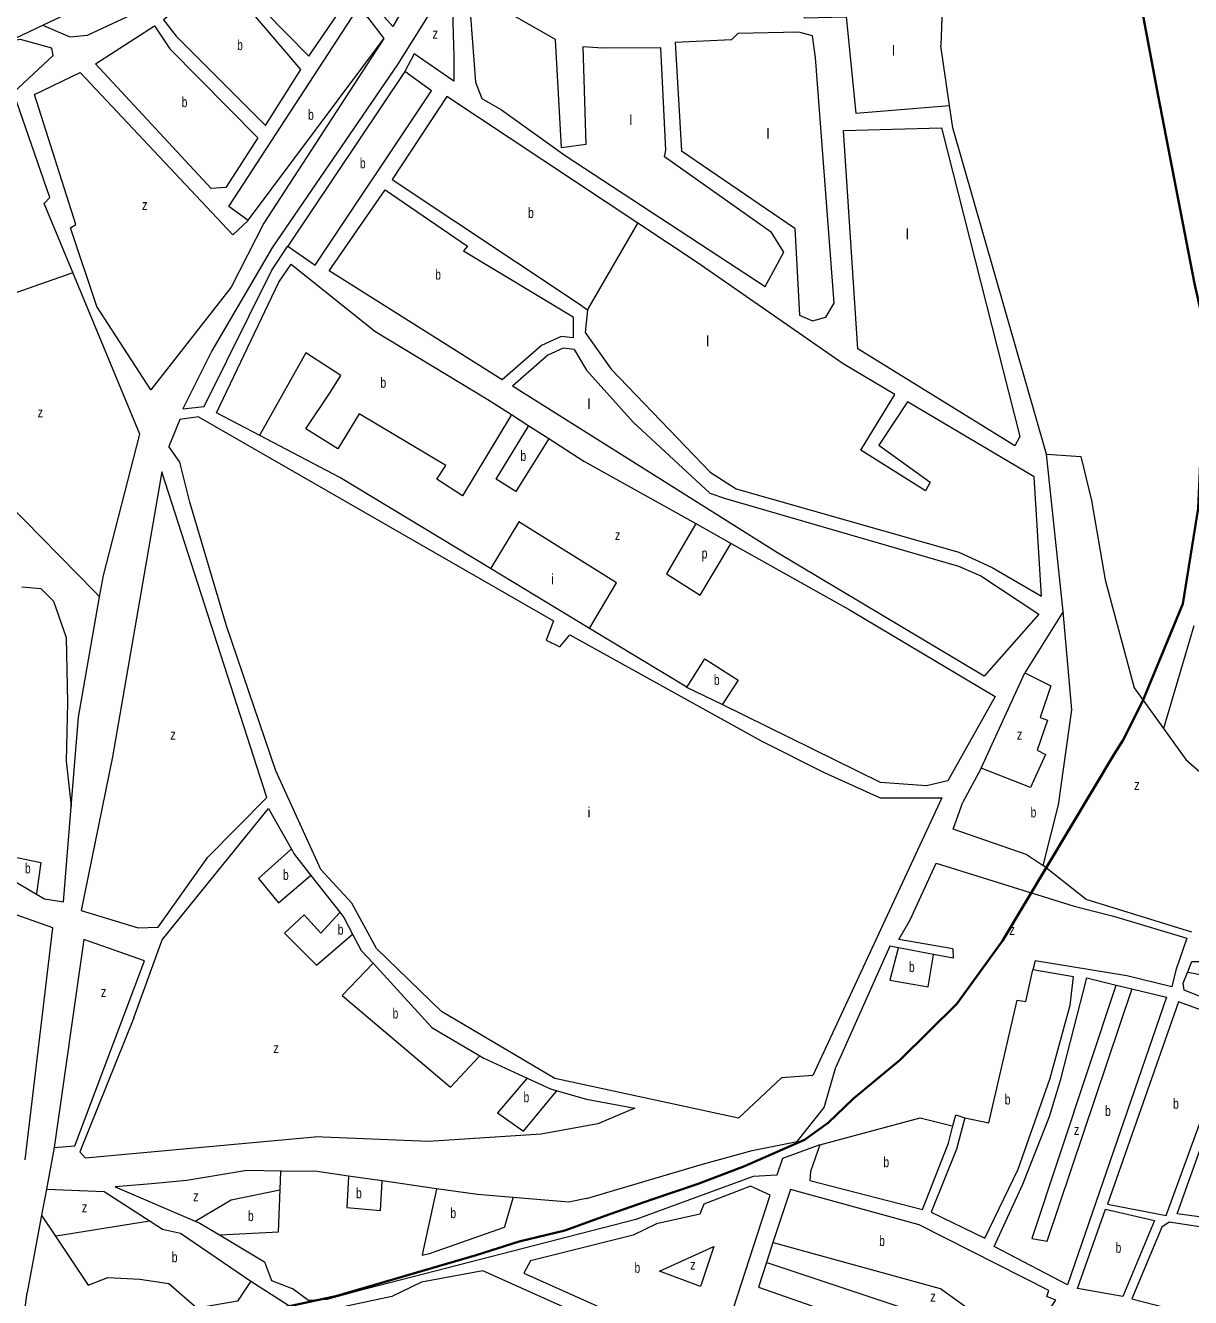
# Model space of a CAD drawing. Extents: x 639657 to 671642, y 222838 to 252123.
# Drawn here: x 646943 to 648074, y 234105 to 235340 of the extents above; entities that cross this region are included whole.
import ezdxf

# ---------------------------------------------------------------- set-up
doc = ezdxf.new("R2010")
doc.units = 0
doc.header["$LTSCALE"] = 4
for name, color, linetype, lineweight in [('1', 7, 'Continuous', 13), ('21', 7, 'Continuous', 13), ('57', 7, 'Continuous', 35)]:
    doc.layers.add(name, color=color, linetype=linetype, lineweight=lineweight)
doc.layers.add('7', color=7, linetype='Continuous')

msp = doc.modelspace()

# ---------------------------------------------------------------- linework, layer by layer
at = {"layer": '1'}
for p, q in [((647144.641, 235136.525), (647159.531, 235150.532)), ((647950.552, 234770.922), (647934.4, 234923.67)), ((647950.552, 234770.922), (647913.58, 234711.44)), ((647870.96, 234618.78), (647913.58, 234711.44)), ((647870.96, 234618.78), (647853.32, 234585.79)), ((647915.54, 234534.59), (647931.11, 234524.53)), ((647972.81, 234491.34), (647931.11, 234524.53)), ((648075.39, 234459.63), (647972.81, 234491.34)), ((646939.271, 234066.351), (646944.98, 234109.88))]:
    msp.add_line(p, q, dxfattribs=at)
for points in [[(647199.59, 235439.27), (647140.33, 235394.43), (647175.84, 235353.17), (647218.45, 235309.8), (647256.57, 235365.91)], [(647132.42, 235388.79), (647077.45, 235345.27), (647089.58, 235329.44), (647176.52, 235242.72), (647210.58, 235296.86)], [(647457.773, 235326.202), (647401.48, 235357.97), (647384.7, 235360.67), (647375.53, 235348.79), (647380.23, 235284.78), (647386.35, 235268.7), (647405.33, 235257.64), (647467.29, 235213.53), (647661.3, 235086.41), (647679.36, 235119.62), (647667.63, 235138.89), (647563.58, 235212.18), (647564.83, 235218.63), (647560.13, 235318.11), (647503.82, 235317.55), (647484.47, 235318.94), (647487.21, 235224.18), (647463.59, 235220.82)], [(647011.3, 235302.53), (647068.68, 235339.2), (647083.64, 235316.94), (647169.08, 235230.64), (647137.99, 235182.53), (647123.6, 235181.58)], [(647574.07, 235323.13), (647580.31, 235217.87), (647690.18, 235142.89), (647694.57, 235058.46), (647707.5, 235052.95), (647720.37, 235056.69), (647728.24, 235070.06), (647710.21, 235308.7), (647707.29, 235329.53), (647694.15, 235333.1), (647634.84, 235331.88), (647628.65, 235325.83)], [(647224.65, 235106.98), (647337.51, 235276.35), (647311.82, 235295.11), (647198.1, 235125.51)], [(647903.74, 234931.79), (647751.3, 235025.71), (647737.52, 235237.73), (647832.69, 235240.2), (647908.72, 234940.71)], [(646971.4, 234250.8), (646991.38, 234252.21), (647059.05, 234431.84), (647000.03, 234452.55)], [(648050.92, 234396.54), (647954.88, 234117.5), (647883.51, 234154.68), (647911.5, 234215.23), (647937.53, 234280.93), (647948.48, 234317.1), (647973.45, 234415.25), (648002.078, 234408.336), (648017.39, 234404.638)], [(647993.55, 234195.85), (648050.7, 234184.54), (648118.84, 234371.56), (648062.64, 234392.11)], [(648061.43, 234186.32), (648126.38, 234368.37), (648166.87, 234352.9), (648130.68, 234177.03)], [(647614.46, 234044.95), (647666.34, 234204.51), (647647.16, 234213.2), (647601.91, 234195.74), (647598.11, 234185.83), (647556.04, 234176.76), (647533.32, 234165.66), (647433.54, 234140.78), (647427.16, 234128.7)], [(648008.46, 234105.96), (647964.58, 234113.91), (647991.69, 234190.99), (648039.33, 234179.75)], [(648017.41, 234103.94), (648110.38, 234079.94), (648127.52, 234166.9), (648053.53, 234178.11), (648046.25, 234173.34)], [(647606.2, 234032.98), (647387.39, 234130.83), (647327.92, 234120.15), (647299.21, 234106.22), (647238.46, 234093.18), (647236.17, 234081.99), (647372.86, 234000.26), (647487.26, 233943.08), (647558.42, 233921.75)]]:
    msp.add_lwpolyline(points, close=True, dxfattribs=at)
for points in [[(647326.847, 235393.309), (647316.95, 235367.99), (647299.984, 235338.746), (647248.86, 235396.38), (647293.847, 235432.929)], [(646927.135, 235324.15), (646927.635, 235324.388), (646960.334, 235339.941), (647121.629, 235416.66)], [(646960.334, 235339.941), (646960.834, 235339.729), (646986.678, 235328.759), (647003.572, 235330.296), (647061.165, 235357.185), (647112.615, 235390.989), (647122.597, 235404.049), (647121.629, 235416.66)], [(647363.673, 235396.456), (647304.558, 235301.827), (647183.371, 235124.398), (647124.256, 235023.855), (647096.176, 234967.67), (647116.96, 234969.86)], [(647363.673, 235396.456), (647357.761, 235365.406), (647359.239, 235309.22), (647359.239, 235285.563), (647320.814, 235312.177), (647312.083, 235295.61), (647311.82, 235295.11)], [(647695.711, 235388.496), (647699.22, 235347.1), (647740.05, 235348.21), (647749.45, 235254.57), (647840.45, 235261.839)], [(647159.531, 235150.532), (647140.9, 235164.06), (647264.6, 235354.14)], [(647264.6, 235354.14), (647275.38, 235347.75), (647291.2, 235327), (647174.784, 235147.736)], [(646931.74, 235274.76), (646970.42, 235310.66), (646969.08, 235317.75), (646938.73, 235325.94), (646927.135, 235324.15)], [(647065.28, 234985.89), (647012.76, 235066.8), (646987.15, 235143.14), (646992.28, 235146.4), (646952.17, 235272.52), (646996.53, 235294.06), (647144.641, 235136.525)], [(646989.415, 235099.809), (646961.64, 235166.84), (646967.19, 235172.68), (646931.74, 235274.76)], [(647537.881, 235147.794), (647352.37, 235270.86), (647299.36, 235190.17), (647480.86, 235069.63), (647488.85, 235063.66)], [(647934.4, 234923.67), (647843.67, 235240.31), (647840.45, 235261.839)], [(647406.299, 234995.789), (647238.22, 235101.47), (647292.54, 235180.24), (647372.41, 235125.49), (647368.56, 235120.96), (647474.92, 235056.92), (647475.049, 235036.541)], [(647174.784, 235147.736), (647143.11, 235085.64), (647065.28, 234985.89)], [(647929.67, 234785.89), (647922.51, 234901.47), (647799.41, 234974.3), (647771.79, 234932.25), (647821.66, 234896.51), (647817.18, 234887.99), (647754.3, 234927.43), (647787.35, 234981.43), (647736.99, 235011.23), (647595.38, 235109.65), (647537.881, 235147.794)], [(647116.96, 234969.86), (647182.55, 235102.21), (647197.766, 235125.01), (647198.1, 235125.51)], [(647128.88, 234963.633), (647189.283, 235090.391), (647201.495, 235107.846)], [(647201.495, 235107.846), (647282.65, 235042.86), (647392.24, 234976.69), (647415.112, 234962.013), (647432.029, 234951.157), (647451.466, 234938.684)], [(647015.445, 234785.175), (647019.11, 234805.95), (647054.37, 234943.05), (646989.415, 235099.809)], [(647488.85, 235063.66), (647486.62, 235041.73), (647511.77, 235006.21), (647608.04, 234906.01), (647633.28, 234890.04), (647849.24, 234828.6), (647881.78, 234813.54), (647929.67, 234785.89)], [(647475.049, 235036.541), (647463.457, 235037.747), (647444.458, 235029.194), (647406.299, 234995.789)], [(647475.98, 235025.33), (647465.278, 235026.443), (647450.5, 235019.79), (647416.067, 234989.647)], [(647475.98, 235025.33), (647488.14, 235004.99), (647533.16, 234954.77), (647607.73, 234885.59), (647623.03, 234880.52), (647849.11, 234815.06), (647870.66, 234805.52), (647926.99, 234768.26), (647874.06, 234707.98)], [(647874.06, 234707.98), (647673.22, 234827.96), (647416.067, 234989.647)], [(647111.44, 234959.73), (647093.221, 234957.32), (647082.504, 234930.929)], [(647111.44, 234959.73), (647455.9, 234761.75), (647448.93, 234743.01), (647462.08, 234736.64), (647471.68, 234748.31), (647657.58, 234645.42), (647718.6, 234614.63), (647773.13, 234590.03), (647832.88, 234590.18), (647707.82, 234320.59), (647677.24, 234318.25), (647635.4, 234279.28)], [(647394.924, 234812.577), (647248.71, 234901.04), (647170.777, 234941.748), (647128.88, 234963.633)], [(647635.4, 234279.28), (647457.15, 234317.78), (647347.14, 234382.66), (647284.21, 234443.95), (647260.09, 234487.86), (647230.22, 234520.34), (647186.36, 234616.25), (647138.72, 234756.85), (647103.08, 234876.92), (647093.221, 234915.92), (647082.504, 234930.929)], [(647451.466, 234938.684), (647485.46, 234916.87), (647593.954, 234856.167), (647628.297, 234836.952)], [(646997.49, 234480.68), (647052.83, 234464.04), (647072.38, 234464.59), (647120.54, 234532.57), (647177.78, 234590.51), (647075.66, 234906.431)], [(647075.66, 234906.431), (647027.94, 234630), (646997.49, 234480.68)], [(647628.297, 234836.952), (647742.33, 234773.15), (647884.71, 234688.49)], [(647585.527, 234697.289), (647585.26, 234697.42), (647490.829, 234754.553), (647394.924, 234812.577)], [(646987.762, 234581.467), (646994.82, 234668.27), (647015.445, 234785.175)], [(647884.71, 234688.49), (647838.79, 234606.55), (647817.98, 234601.7), (647773.47, 234604.86), (647619.54, 234680.561), (647585.527, 234697.289)], [(647915.54, 234534.59), (647843.81, 234559.73), (647853.32, 234585.79)], [(646954.163, 234496.678), (646961.95, 234492.07), (646980.24, 234488.96), (646987.762, 234581.467)], [(647048.64, 234376.55), (647076.11, 234452.36), (647179.35, 234579.77), (647201.529, 234540.392)], [(646887.227, 234548.986), (646914.5, 234520.15), (646927.332, 234512.556), (646954.163, 234496.678)], [(648071.301, 234420.68), (648075.39, 234431.15), (648142.28, 234431.24), (648204.25, 234449.42), (648245.56, 234488.83), (648245.57, 234541.38), (648240.7, 234551.44), (648262.51, 234544.71), (648342.83, 234369.89)], [(647201.529, 234540.392), (647204.56, 234535.01), (647220.433, 234514.8), (647248.564, 234478.982)], [(647802.02, 234471.8), (647827.25, 234526.75), (647961.2, 234484.8)], [(646943.317, 234238.668), (646970.08, 234463.97), (646938.884, 234474.813), (646903.312, 234487.177), (646897.191, 234489.305)], [(647961.2, 234484.8), (647999.51, 234475.36), (648070.65, 234453.71), (648060.08, 234422.87)], [(647248.564, 234478.982), (647252.43, 234474.06), (647261.029, 234457.78)], [(647843.574, 234443.382), (647791.18, 234452.61), (647802.02, 234471.8)], [(647261.029, 234457.78), (647269.4, 234441.93), (647280.822, 234429.474)], [(647790.714, 234444.529), (647782.4, 234446.11), (647730.05, 234328.67)], [(647843.574, 234443.382), (647843.73, 234434.45), (647824.757, 234438.057), (647790.714, 234444.529)], [(647280.822, 234429.474), (647337.99, 234367.13), (647384.412, 234339.63)], [(647874.65, 234162.58), (647907.12, 234229.6), (647938.16, 234317.9), (647957.28, 234388.72), (647960.76, 234416.46), (647921.119, 234423.278)], [(648012.37, 234417.28), (647923.49, 234431.71), (647921.119, 234423.278)], [(648060.08, 234422.87), (648056.09, 234406.56), (648012.37, 234417.28)], [(648271.66, 234336.15), (648170.26, 234362.9), (648067.93, 234403.4), (648067.24, 234410.28), (648071.301, 234420.68)], [(647048.64, 234376.55), (646996.15, 234246.43), (647001.34, 234240.66), (647224.31, 234261.14)], [(647384.412, 234339.63), (647388.26, 234337.35), (647430.467, 234318.026)], [(647487.54, 234201.06), (647488.04, 234201.209), (647600.498, 234234.648), (647648.685, 234247.796), (647692.491, 234256.561), (647718.775, 234289.431), (647730.05, 234328.67)], [(647430.467, 234318.026), (647453.13, 234307.65), (647459.373, 234305.843)], [(647459.373, 234305.843), (647488.02, 234297.55), (647534.92, 234289.02), (647499.13, 234273.55), (647443.95, 234263.54), (647334.6, 234256.65), (647224.31, 234261.14)], [(647855.232, 234279.523), (647847.03, 234249.23), (647822.48, 234187.83), (647874.65, 234162.58)], [(647843.548, 234271.609), (647846.312, 234282.461), (647855.232, 234279.523)], [(647814.08, 234190.57), (647839.26, 234254.77), (647843.548, 234271.609)], [(646971.4, 234250.8), (646963.825, 234210.396), (646959.038, 234184.864), (646944.98, 234109.88)], [(647714.395, 234253.274), (647678.254, 234240.126), (647672.778, 234223.691), (647649.78, 234222.595), (647535.884, 234180.96), (647264.286, 234110.837), (647235.812, 234103.168), (647218.289, 234102.072), (647202.23, 234113.8)], [(647714.395, 234253.274), (647705.31, 234227.31), (647704.72, 234218.71), (647814.08, 234190.57)], [(647191.479, 234227.862), (647158.32, 234228.29), (647099.92, 234218.7), (647065.771, 234215.537), (647030.447, 234212.464), (647108.111, 234179.238)], [(647257.111, 234222.986), (647226.45, 234227.41), (647191.479, 234227.862)], [(647416.51, 234202.148), (647382.2, 234204.94), (647342.507, 234210.666), (647289.622, 234218.296), (647257.111, 234222.986)], [(646963.825, 234210.396), (646964.325, 234210.373), (647019.696, 234207.854), (647064.468, 234179.117)], [(647487.54, 234201.06), (647470.8, 234197.73), (647416.51, 234202.148)], [(647893.09, 234030.74), (647943.37, 234102.61), (647934.75, 234106.21), (647936.65, 234111.8), (647810.95, 234175.51), (647685.86, 234210), (647668.969, 234158.379), (647662.676, 234139.148)], [(647064.468, 234179.117), (647076.35, 234171.49), (647094, 234167.52), (647162.21, 234121.08)], [(647108.111, 234179.238), (647112.64, 234177.3), (647131.832, 234165.787)], [(647131.832, 234165.787), (647175.42, 234139.64), (647182.19, 234121.63), (647202.23, 234113.8)], [(647662.676, 234139.148), (647654.86, 234115.26), (647745.54, 234083.35), (647801.95, 234067.79), (647844.17, 234051.29), (647893.09, 234030.74)], [(647162.21, 234121.08), (647205.147, 234093.307), (647200.767, 234084.541), (647172.293, 234084.541), (647141.628, 234074.68), (647108.774, 234064.819), (647041.969, 234046.193), (646945.892, 234031.918)]]:
    msp.add_lwpolyline(points, dxfattribs=at)
at = {"layer": '21'}
msp.add_line((647840.45, 235261.839), (647831.79, 235319.75), dxfattribs=at)
for points in [[(647836.595, 235446.727), (647833.176, 235356.374), (647831.79, 235319.75)], [(647159.531, 235150.532), (647159.904, 235151.032), (647290.827, 235326.5), (647291.2, 235327)], [(647015.445, 234785.175), (647010.535, 234790.175), (646840.007, 234963.83), (646761.68, 235049.876), (646703.319, 235186.628), (646718.662, 235203.332), (646755.537, 235243.48)], [(646718.662, 235203.332), (646718.881, 235202.832), (646793.933, 235031.438), (646988.915, 235099.634), (646989.415, 235099.809)], [(647488.85, 235063.66), (647489.141, 235064.16), (647537.59, 235147.294), (647537.881, 235147.794)], [(647415.112, 234962.013), (647414.812, 234961.513), (647367.738, 234883.022), (647342.614, 234899.286), (647351.482, 234912.593), (647267.243, 234962.865), (647246.552, 234928.858), (647215.517, 234948.079), (647239.163, 234983.565), (647249.508, 234999.829), (647215.517, 235022.008), (647171.056, 234942.248), (647170.777, 234941.748)], [(647451.466, 234938.684), (647451.154, 234938.184), (647419.464, 234887.458), (647400.252, 234899.286), (647431.723, 234950.657), (647432.029, 234951.157)], [(647934.4, 234923.67), (647934.9, 234923.637), (647967.76, 234921.468), (647978.105, 234878.589), (647991.406, 234801.703), (648019.485, 234696.724), (648048.043, 234657.229)], [(647490.829, 234754.553), (647491.125, 234755.053), (647517.005, 234798.743), (647422.42, 234857.886), (647395.227, 234813.077), (647394.924, 234812.577)], [(647593.954, 234856.167), (647593.664, 234855.667), (647565.775, 234807.615), (647598.288, 234786.915), (647627.997, 234836.452), (647628.297, 234836.952)], [(646939.835, 234794.812), (646958.265, 234793.275), (646970.551, 234780.983), (646982.838, 234745.642), (646984.374, 234682.644), (646982.838, 234625.793), (646987.706, 234581.964), (646987.762, 234581.467)], [(647931.11, 234524.53), (647945.96, 234583.21), (647959.12, 234675.59), (647950.552, 234770.922)], [(648048.043, 234657.229), (648048.192, 234657.729), (648077.94, 234757.45)], [(647585.527, 234697.289), (647585.825, 234697.767), (647602.722, 234724.815), (647635.235, 234704.115), (647619.873, 234681.061), (647619.54, 234680.561)], [(647913.58, 234711.44), (647938.59, 234698.7), (647928.25, 234667.91), (647935.57, 234665.59), (647925.44, 234636.3), (647933.42, 234632.27), (647918.79, 234600.16), (647870.96, 234618.78)], [(648048.043, 234657.229), (648069.733, 234627.232), (648118.504, 234584.353), (648231.79, 234495.283), (648232.29, 234494.89)], [(647201.529, 234540.392), (647201.029, 234539.944), (647169.703, 234511.903), (647188.915, 234488.246), (647219.933, 234514.379), (647220.433, 234514.8)], [(646927.332, 234512.556), (646927.374, 234513.056), (646929.084, 234533.601), (646958.265, 234527.455), (646954.23, 234497.178), (646954.163, 234496.678)], [(647248.564, 234478.982), (647248.114, 234478.482), (647230.296, 234458.674), (647214.039, 234476.417), (647194.827, 234458.674), (647225.862, 234427.624), (647260.529, 234457.351), (647261.029, 234457.78)], [(647790.714, 234444.529), (647790.579, 234444.029), (647782.293, 234413.242), (647819.529, 234406.668), (647824.674, 234437.557), (647824.757, 234438.057)], [(647280.822, 234429.474), (647280.347, 234428.974), (647250.986, 234398.053), (647355.916, 234309.338), (647383.942, 234339.13), (647384.412, 234339.63)], [(647855.232, 234279.523), (647878.62, 234274.616), (647905.886, 234393.651), (647914.561, 234392.411), (647921.119, 234423.278)], [(648283.44, 234379.88), (648282.94, 234379.976), (648071.801, 234420.584), (648071.301, 234420.68)], [(648002.078, 234408.336), (648001.911, 234407.836), (647920.138, 234162.402), (647935.011, 234159.922), (648017.222, 234404.138), (648017.39, 234404.638)], [(647430.467, 234318.026), (647430.042, 234317.526), (647401.731, 234284.202), (647426.855, 234266.46), (647458.96, 234305.343), (647459.373, 234305.843)], [(647714.395, 234253.274), (647811.694, 234279.576), (647843.048, 234271.734), (647843.548, 234271.609)], [(647190.696, 234209.844), (647191.457, 234227.362), (647191.479, 234227.862)], [(647257.111, 234222.986), (647257.083, 234222.486), (647255.42, 234192.531), (647287.934, 234189.574), (647289.593, 234217.796), (647289.622, 234218.296)], [(647108.111, 234179.238), (647143.101, 234199.924), (647190.196, 234209.74), (647190.696, 234209.844)], [(647131.832, 234165.787), (647132.332, 234165.814), (647188.915, 234168.874), (647190.696, 234209.844)], [(647342.507, 234210.666), (647342.398, 234210.166), (647328.582, 234146.573), (647328.473, 234146.072)], [(647416.51, 234202.148), (647416.367, 234201.648), (647408.408, 234173.773), (647408.265, 234173.274)], [(646959.038, 234184.864), (646959.371, 234184.365), (646972.612, 234164.496)], [(647064.468, 234179.117), (647063.968, 234179.037), (646973.112, 234164.576), (646972.612, 234164.496)], [(646972.612, 234164.496), (647004.18, 234117.124), (647023.393, 234124.517), (647054.428, 234123.038), (647082.508, 234118.602), (647110.126, 234094.655)], [(647328.473, 234146.072), (647336.56, 234148.14), (647408.265, 234173.274)], [(647662.676, 234139.148), (647663.176, 234138.981), (647829.045, 234083.666), (647879.859, 234057.627), (647888.535, 234072.506), (647831.524, 234113.424), (647669.469, 234158.241), (647668.969, 234158.379)], [(647162.21, 234121.08), (647149.22, 234101.45), (647110.126, 234094.655)]]:
    msp.add_lwpolyline(points, dxfattribs=at)
msp.add_lwpolyline([(647611.45, 234154.697), (647598.525, 234115.904), (647558.865, 234130.783)], close=True, dxfattribs=at)
at = {"layer": '57'}
for points in [[(649431.73, 232002.995), (649399.994, 232070.308), (649353.025, 232164.294), (649236.203, 232405.189), (649089.828, 232739.384), (648914.202, 233126.457), (648685.944, 233640.163), (648499.009, 234038.457), (648378.361, 234308.787), (648275.477, 234548.58), (648171.383, 234786.42), (648107.014, 234960.761), (648078.134, 235089.132), (648042.869, 235271.292), (648019.786, 235394.046), (648011.928, 235560.15), (648011.719, 235757.044), (648014.054, 235904.557)], [(648085.047, 235058.403), (648087.089, 234994.793), (648081.583, 234870.755), (648066.631, 234778.388), (648027.612, 234683.441), (648008.585, 234645.639), (648000, 234632.542)], [(648000, 234632.542), (647891.632, 234451.243), (647847.53, 234390.093), (647792.434, 234335.645), (647747.248, 234298.136), (647722.436, 234274.516), (647699.587, 234258.006), (647641.193, 234232.604), (647596.478, 234215.429), (647551.326, 234200.123), (647510.74, 234185.892), (647467.006, 234170.281), (647422.772, 234159.517), (647380.959, 234146.239), (647244.558, 234106.515), (647142.43, 234084.324)]]:
    msp.add_lwpolyline(points, dxfattribs=at)

# ---------------------------------------------------------------- texts
at = {"layer": '7'}
for s, width, p in [('b', 0.75, (647148.907, 235315.755)), ('z', 0.8, (647338.549, 235326.963)), ('b', 0.75, (647095.026, 235260.39)), ('b', 0.75, (647217.793, 235248.125)), ('b', 0.75, (647268.039, 235201.045)), ('z', 0.8, (647056.557, 235160.507)), ('b', 0.75, (647431.287, 235152.861)), ('b', 0.75, (647341.136, 235092.979)), ('b', 0.75, (647287.933, 234988)), ('z', 0.8, (646955.193, 234959.221)), ('b', 0.75, (647423.898, 234917.029)), ('z', 0.8, (647515.527, 234840.143)), ('p', 0.75, (647599.766, 234822.4)), ('b', 0.75, (647611.589, 234699.679)), ('z', 0.8, (647083.986, 234646.453)), ('z', 0.8, (647905.688, 234646.453)), ('z', 0.8, (648019.485, 234597.66)), ('b', 0.75, (647918.989, 234571.046)), ('b', 0.75, (646942.907, 234516.699)), ('b', 0.75, (647193.349, 234510.424)), ('b', 0.75, (647246.553, 234457.196)), ('z', 0.8, (647898.381, 234457.069)), ('b', 0.75, (647800.911, 234420.912)), ('z', 0.8, (647016.625, 234396.848)), ('b', 0.75, (647299.757, 234375.874)), ('z', 0.8, (647184.03, 234342.301)), ('b', 0.75, (647426.855, 234294.553)), ('b', 0.75, (647893.964, 234292.425)), ('b', 0.75, (647991.25, 234281.254)), ('b', 0.75, (648057.309, 234288.325)), ('z', 0.8, (647961.037, 234262.837)), ('b', 0.75, (647776.117, 234231.557)), ('z', 0.8, (647106.154, 234198.445)), ('b', 0.75, (647264.287, 234201.402)), ('z', 0.8, (646998.195, 234187.88)), ('b', 0.75, (647159.358, 234179.224)), ('b', 0.75, (647355.916, 234182.181)), ('b', 0.75, (647772.026, 234155.088)), ('b', 0.75, (648001.492, 234148.475)), ('b', 0.75, (647085.464, 234139.302)), ('b', 0.75, (647534.585, 234129.075)), ('z', 0.8, (647588.61, 234132.023)), ('z', 0.8, (647821.609, 234101.025))]:
    msp.add_text(s, height=10, dxfattribs=dict(at, width=width)).set_placement(p)
for s, p in [('l', (647784.501, 235310.329)), ('l', (647529.566, 235243.054)), ('l', (647662.576, 235229.747)), ('l', (647797.802, 235132.161)), ('l', (647604.199, 235028.375)), ('l', (647488.925, 234967.3)), ('i', (647453.456, 234797.265)), ('i', (647488.925, 234571.043))]:
    msp.add_text(s, height=10, dxfattribs=at).set_placement(p)

doc.saveas('drawing.dxf')
